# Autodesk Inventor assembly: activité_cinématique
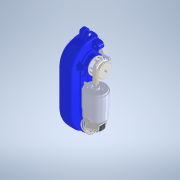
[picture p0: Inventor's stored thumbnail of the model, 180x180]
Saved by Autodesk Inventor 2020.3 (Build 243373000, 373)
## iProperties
Created: 2020-12
Part Number: activité_cinématique
Document SubType Name: Assembly
Designer: M. Fichot
Author: M. Fichot
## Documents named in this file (7)
- D:\travail\année 2020-2021\2I2D\laveur de vitre\activité_cinématique.iam
- D:\travail\année 2020-2021\2I2D\laveur de vitre\activité cinématique classe fixe.iam
- D:\travail\année 2020-2021\2I2D\laveur de vitre\Roue Moteur.iam
- D:\travail\année 2020-2021\2I2D\laveur de vitre\satellite.ipt
- D:\travail\année 2020-2021\2I2D\laveur de vitre\porte sattelites inventor complet.iam
- D:\travail\année 2020-2021\2I2D\laveur de vitre\roue dentée etagée.iam
- D:\travail\année 2020-2021\2I2D\laveur de vitre\axe moteur cheville inventor.iam
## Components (7 placed, 6 different names)
1. activité cinématique classe fixe:1 [sub-assembly] — Logement:1, Logement:4, Logement:5
2. Roue Moteur:1 [sub-assembly] — Logement:1, Logement:2, Placage:1
3. Engrenage cylindrique2:1 — Logement:2
4. Engrenage cylindrique2:2 — Logement:3
5. porte sattelites inventor complet:1 [sub-assembly] — Placage:1, Logement:3
6. roue dentée etagée:1 [sub-assembly] — Logement:4
7. axe moteur cheville inventor:1 [sub-assembly] — Logement:5
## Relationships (6: Insert 5, Mate 1)
- Logement:1 [Insert]: activité cinématique classe fixe:1 ↔ Roue Moteur:1
- Logement:2 [Insert]: Roue Moteur:1 ↔ Engrenage cylindrique2:1
- Placage:1 [Mate]: Roue Moteur:1 ↔ porte sattelites inventor complet:1
- Logement:3 [Insert]: Engrenage cylindrique2:2 ↔ porte sattelites inventor complet:1
- Logement:4 [Insert]: activité cinématique classe fixe:1 ↔ roue dentée etagée:1
- Logement:5 [Insert]: activité cinématique classe fixe:1 ↔ axe moteur cheville inventor:1
